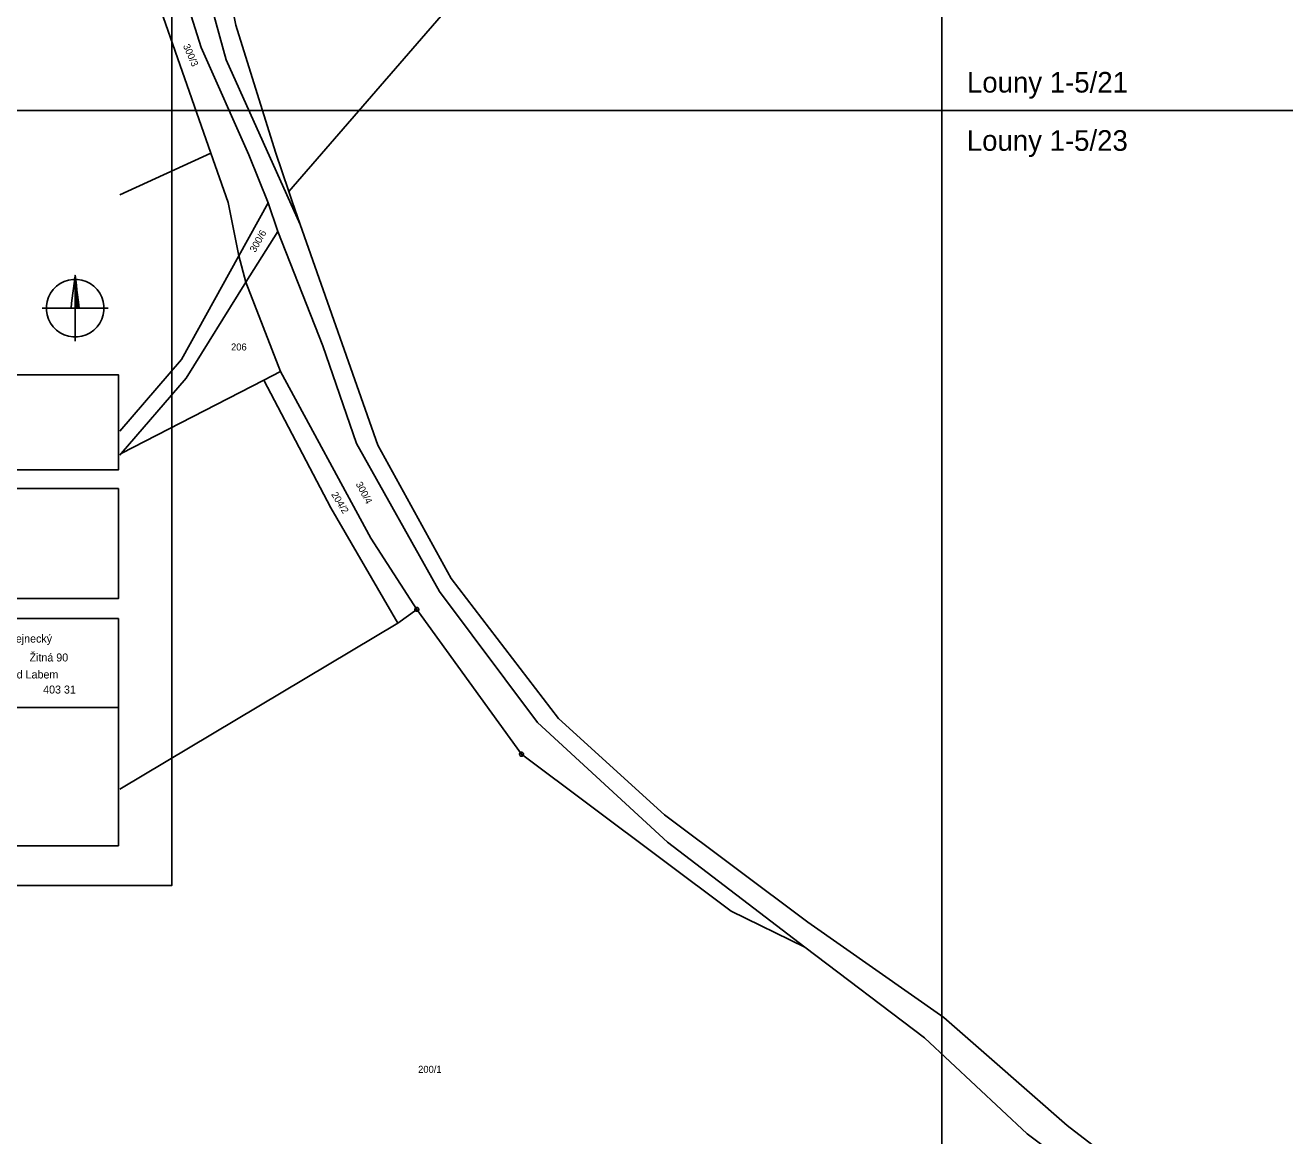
# Model space of a CAD drawing. Extents: x -780000 to -777378, y -1011169 to -1009297.
# Drawn here: x -778972.3 to -778666.9, y -1010748.6 to -1010479.3 of the extents above; entities that cross this region are included whole.
import ezdxf

# ---------------------------------------------------------------- set-up
doc = ezdxf.new("R2010")
doc.units = 0
for name, color, linetype in [('Default', 7, 'Continuous'), ('KLADY_ZMVM', 7, 'Continuous'), ('KN_HRANICE', 7, 'Continuous'), ('KN_PARCELY', 7, 'Continuous'), ('LEGENDA', 7, 'Continuous'), ('tabulka', 7, 'Continuous')]:
    doc.layers.add(name, color=color, linetype=linetype)

# ---------------------------------------------------------------- blocks, each defined once
blk = doc.blocks.new('105')
at = {"layer": 'Default'}
blk.add_line((-0.12, 0), (0.12, 0), dxfattribs=at)
blk.add_lwpolyline([(0.15, 0.48), (0.4, 0.3), (0.5, 0.01), (0.4, -0.28), (0.15, -0.46), (-0.16, -0.46), (-0.41, -0.28), (-0.51, 0.01), (-0.41, 0.3), (-0.16, 0.48), (0.15, 0.48)], dxfattribs=at)
blk = doc.blocks.new('SEVER')
at = {"layer": 'Default'}
for points in [[(5.5, 69.8), (16.3, 68.1), (26.7, 64.7), (36.5, 59.7), (45.4, 53.2), (53.2, 45.4), (59.7, 36.5), (64.7, 26.7), (68.1, 16.3), (69.8, 5.5), (69.8, -5.5), (68.1, -16.3), (64.7, -26.7), (59.7, -36.5), (53.2, -45.4), (45.4, -53.2), (36.5, -59.7), (26.7, -64.7), (16.3, -68.1), (5.5, -69.8), (-5.5, -69.8), (-16.3, -68.1), (-26.7, -64.7), (-36.5, -59.7), (-45.4, -53.2), (-53.2, -45.4), (-59.7, -36.5), (-64.7, -26.7), (-68.1, -16.3), (-69.8, -5.5), (-69.8, 5.5), (-68.1, 16.3), (-64.7, 26.7), (-59.7, 36.5), (-53.2, 45.4), (-45.4, 53.2), (-36.5, 59.7), (-26.7, 64.7), (-16.3, 68.1), (-5.5, 69.8), (5.5, 69.8)], [(-10, 0), (-8.5, 12), (-7, 24), (-5.5, 36), (-4, 48), (-2.5, 60), (-1, 72), (0, 80), (1.5, 68), (3, 56), (4.5, 44), (6, 32), (7.5, 20), (9, 8), (10, 0), (9.2, 0.8), (9.2, 5.6), (8.4, 12), (8.4, 0.8), (7.6, 0.8), (7.6, 13.5), (7.6, 18.4), (6.8, 24.8), (6.8, 12.1), (6.8, 0.8), (6, 0.8), (6, 13.5), (6, 26.2), (6, 31.2), (5.2, 36.8), (5.2, 24.1), (5.2, 11.4), (5.2, 0.8), (4.4, 0.8), (4.4, 13.5), (4.4, 26.2), (4.4, 38.9), (4.4, 43.2), (3.6, 50.4), (3.6, 37.7), (3.6, 25), (3.6, 12.3), (3.6, 0.8), (2.8, 0.8), (2.8, 13.5), (2.8, 26.2), (2.8, 38.9), (2.8, 51.6), (2.8, 56), (2, 63.2), (2, 50.5), (2, 37.8), (2, 25.1), (2, 12.4), (2, 0.8), (1.2, 0.8), (1.2, 13.5), (1.2, 26.2), (1.2, 38.9), (1.2, 51.6), (1.2, 64.3), (1.2, 69.6), (0.4, 76), (0.4, 63.3), (0.4, 50.6), (0.4, 37.9), (0.4, 25.2), (0.4, 12.5), (0.4, 0.8)], [(0, 80), (0, 67.3), (0, 54.6), (0, 41.9), (0, 29.2), (0, 16.5), (0, 3.8), (0, -8.9), (0, -21.6), (0, -34.3), (0, -47), (0, -59.7), (0, -72.4), (0, -80)], [(80, 0), (67.3, 0), (54.6, 0), (41.9, 0), (29.2, 0), (16.5, 0), (3.8, 0), (-8.9, 0), (-21.6, 0), (-34.3, 0), (-47, 0), (-59.7, 0), (-72.4, 0), (-80, 0)]]:
    blk.add_lwpolyline(points, dxfattribs=at)

msp = doc.modelspace()

# ---------------------------------------------------------------- linework, layer by layer
at = {"layer": 'KLADY_ZMVM'}
for points in [[(-779108.78, -1010500), (-778750, -1010500), (-778750, -1010000)], [(-778750, -1011000), (-778750, -1010500), (-778125, -1010500)]]:
    msp.add_lwpolyline(points, dxfattribs=at)
at = {"layer": 'KN_HRANICE'}
for p, q in [((-778929.7, -1010437.49), (-778921.17, -1010479.33)), ((-778935.36, -1010444.3), (-778923.56, -1010487.7)), ((-778929.57, -1010484.72), (-778940.29, -1010450.68)), ((-778945.86, -1010456.94), (-778927.24, -1010510.3)), ((-778869.31, -1010474.62), (-778908.34, -1010519.61)), ((-778921.17, -1010479.33), (-778911.59, -1010510.13)), ((-778918, -1010510.77), (-778929.57, -1010484.72)), ((-778923.56, -1010487.7), (-778905.58, -1010527.64)), ((-778949.34, -1010520.45), (-778927.24, -1010510.3)), ((-778927.24, -1010510.3), (-778923.04, -1010522.33)), ((-778913.36, -1010522.39), (-778918, -1010510.77)), ((-778911.59, -1010510.13), (-778908.34, -1010519.61)), ((-778908.34, -1010519.61), (-778907.5, -1010522.06)), ((-778923.04, -1010522.33), (-778920.49, -1010535.22)), ((-778913.36, -1010522.39), (-778920.49, -1010535.22)), ((-778910.96, -1010529.3), (-778913.36, -1010522.39)), ((-778907.5, -1010522.06), (-778905.58, -1010527.64)), ((-778918.72, -1010541.61), (-778910.96, -1010529.3)), ((-778900.07, -1010557.06), (-778910.96, -1010529.3)), ((-778905.58, -1010527.64), (-778886.77, -1010581.17)), ((-778920.49, -1010535.22), (-778934.39, -1010560.4)), ((-778920.49, -1010535.22), (-778918.72, -1010541.61)), ((-778933.19, -1010564.92), (-778918.72, -1010541.61)), ((-778918.72, -1010541.61), (-778910.38, -1010563.3)), ((-778891.89, -1010580.73), (-778900.07, -1010557.06)), ((-778934.39, -1010560.4), (-778949.34, -1010577.76)), ((-778914.41, -1010565.37), (-778910.38, -1010563.3)), ((-778888.45, -1010603.65), (-778910.38, -1010563.3)), ((-778949, -1010583.2), (-778933.19, -1010564.92)), ((-778949, -1010583.2), (-778914.41, -1010565.37)), ((-778914.41, -1010565.37), (-778898.15, -1010596.34)), ((-778871.79, -1010616.66), (-778891.89, -1010580.73)), ((-778886.77, -1010581.17), (-778868.96, -1010613.49)), ((-778949.34, -1010583.59), (-778949, -1010583.2)), ((-778898.15, -1010596.34), (-778881.89, -1010624.28)), ((-778888.45, -1010603.65), (-778877.27, -1010620.97)), ((-778868.96, -1010613.49), (-778842.93, -1010647.4)), ((-778848.04, -1010648.37), (-778871.79, -1010616.66)), ((-778877.27, -1010620.97), (-778881.89, -1010624.28)), ((-778877.27, -1010620.97), (-778851.92, -1010656.09)), ((-778881.89, -1010624.28), (-778949.34, -1010664.57)), ((-778816.52, -1010677.44), (-778848.04, -1010648.37)), ((-778842.93, -1010647.4), (-778817.25, -1010670.8)), ((-778851.92, -1010656.09), (-778801.09, -1010694.14)), ((-778817.25, -1010670.8), (-778782.47, -1010696.78)), ((-778783.19, -1010702.88), (-778816.52, -1010677.44)), ((-778801.09, -1010694.14), (-778783.19, -1010702.88)), ((-778782.47, -1010696.78), (-778749.49, -1010719.92)), ((-778783.19, -1010702.88), (-778754.23, -1010724.83)), ((-778749.49, -1010719.92), (-778738.54, -1010729.52)), ((-778754.23, -1010724.83), (-778729.33, -1010748.14)), ((-778738.54, -1010729.52), (-778719.6, -1010746.13)), ((-778719.6, -1010746.13), (-778676.79, -1010778.85)), ((-778729.33, -1010748.14), (-778714.89, -1010758.88))]:
    msp.add_line(p, q, dxfattribs=at)
at = {"layer": 'LEGENDA'}
msp.add_lwpolyline([(-779530.66, -1010687.91), (-778936.66, -1010687.91), (-778936.66, -1010267.91), (-779530.66, -1010267.91)], close=True, dxfattribs=at)
at = {"layer": 'tabulka'}
for p, q in [((-779108.28, -1010623.16), (-778949.63, -1010623.16)), ((-779108.28, -1010644.77), (-778949.63, -1010644.77))]:
    msp.add_line(p, q, dxfattribs=at)
for points in [[(-779108.28, -1010564.07), (-778949.63, -1010564.07), (-778949.63, -1010587.13), (-779108.28, -1010587.13)], [(-779108.28, -1010591.65), (-778949.63, -1010591.65), (-778949.63, -1010618.34), (-779108.28, -1010618.34)]]:
    msp.add_lwpolyline(points, close=True, dxfattribs=at)
msp.add_lwpolyline([(-778949.63, -1010623.16), (-778949.63, -1010678.29), (-779108.28, -1010678.29), (-779108.28, -1010623.16)], dxfattribs=at)

# ---------------------------------------------------------------- block references
at = {"layer": 'KN_PARCELY'}
for p in [(-778877.27, -1010620.97), (-778851.92, -1010656.09)]:
    msp.add_blockref('105', p, dxfattribs=at)
at = {"layer": 'LEGENDA', "xscale": 0.1, "yscale": 0.10000000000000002}
msp.add_blockref('SEVER', (-778960.14, -1010547.92), dxfattribs=at)

# ---------------------------------------------------------------- texts
at = {"layer": 'KLADY_ZMVM'}
for s, p in [('Louny 1-5/21', (-778743.91, -1010495.64)), ('Louny 1-5/23', (-778743.95, -1010509.76))]:
    msp.add_text(s, height=5, dxfattribs=at).set_placement(p)
at = {"layer": 'KN_PARCELY'}
for s, rotation, p in [('300/3', 293.641, (-778934.03, -1010484.3)), ('300/6', 61.077, (-778916.44, -1010534.54)), ('300/4', 297.995, (-778892.17, -1010590.55)), ('204/2', 301.605, (-778898.12, -1010593.08))]:
    msp.add_text(s, height=1.7, rotation=rotation, dxfattribs=at).set_placement(p)
for s, p in [('206', (-778922.34, -1010558.18)), ('200/1', (-778876.98, -1010733.34))]:
    msp.add_text(s, height=1.7, dxfattribs=at).set_placement(p)
at = {"layer": 'tabulka'}
for s, p in [('Ing. Jiří Mlejnecký', (-778986.49, -1010629.01)), ('Žitná 90', (-778971.2, -1010633.59)), ('Ústí nad Labem', (-778982.53, -1010637.71)), ('403 31', (-778967.9, -1010641.37))]:
    msp.add_text(s, height=1.94, dxfattribs=at).set_placement(p)

doc.saveas('drawing.dxf')
